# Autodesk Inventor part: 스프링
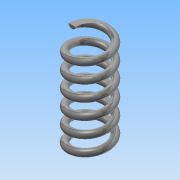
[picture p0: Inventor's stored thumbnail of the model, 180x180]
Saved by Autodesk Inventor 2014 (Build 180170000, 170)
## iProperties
Created: 2015-12
Part Number: 스프링
Material: 강철, 탄소
Document SubType Name: Modeling
Designer: imci
Density: 7.87 g/cm^3
Appearance: 반연마
Mass: 16.5223 g
Surface Area: 28.4933 cm^2
Volume: 2.09941 cm^3
Author: imci
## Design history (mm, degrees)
sketch "스케치1"
  geometry: L1 (0, 0)-(8, 0); L2 (0, 0)-(0, 42); L3 (0, 42)-(54.131, 42); C1 r 1.5 at (8, 0)
  constraints: 6 end point, 2 perpendicular, 1 centre point, 1 coincident, 1 horizontal
  dimensions: "d0" = 3 diameter of C1; "d1" = 16 diameter of C1.centre L2; "d2" = 42 distance between parallel lines of L3 L1 (derived)
feature "코일1" sketch "스케치1" pitch "d3" = 10; turns "d5" = 6; dims "d4" = 42 (= d2), "d6" = 0, angle "d7" = 90 deg, angle "d8" = 90 deg, "d9" = 0, "d10" = 0
sketch "스케치2"
  geometry: C1 r 27.666 at (0, 0); 1 further point
  constraints: 1 centre point, 1 coincident
extrude "돌출1" cut sketch "스케치2" stored distance "d11" = 0; taper "d12" = 0 deg
node "작업 평면1"
sketch "스케치3"
  geometry: C1 r 14.92 at (0, 0); 1 further point
  constraints: 1 centre point, 1 coincident
extrude "돌출2" cut sketch "스케치3" stored distance "d13" = 0; taper "d14" = 0 deg
node "솔리드1"
